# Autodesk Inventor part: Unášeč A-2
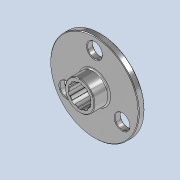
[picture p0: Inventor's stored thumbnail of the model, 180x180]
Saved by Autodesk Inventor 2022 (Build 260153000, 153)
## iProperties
Created: 2025-05
Part Number: Unášeč A-2
Material: Všeobecné
Document SubType Name: Modeling
Designer: jbart
Density: 1 g/cm^3
Appearance: Broušená
Mass: 1373.6 g
Surface Area: 1803.2 cm^2
Volume: 1373.6 cm^3
Author: jbart
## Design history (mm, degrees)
sketch "Náčrt1"
  geometry: L1 (0, 108)-(93.531, -54); L2 (93.531, -54)-(-93.531, -54); L3 (-93.531, -54)-(0, 108); L4 (0, 108)-(0, 0); L5 (0, 0)-(93.531, -54); L6 (0, 0)-(-93.531, -54); C1 r 150 at (0, 0); C2 r 25 at (0, 108); C3 r 25 at (-93.531, -54); C4 r 25 at (93.531, -54); 1 further point
  constraints: 12 end point, 5 coincident, 4 centre point, 1 vertical, 7 other
  dimensions: "d0" = 108 distance of L4.end L1.end; "d1" = 300 diameter of C1; "d2" = 50 diameter of C2; "d3" = 50 diameter of C3; "d4" = 50 diameter of C4
extrude "Vysunutí1" new body sketch "Náčrt1" distance "d5" = 20; taper "d6" = 0 deg
sketch "Náčrt2"
  geometry: C1 r 50 at (0, 0); 1 further point
  constraints: 1 centre point, 1 coincident
  dimensions: "d7" = 100 diameter of C1
extrude "Vysunutí2" join sketch "Náčrt2" distance "d8" = 50; taper "d9" = 0 deg
sketch "Náčrt3"
  geometry: C1 r 36 at (0, 0); 1 further point
  constraints: 1 centre point, 1 coincident
  dimensions: "d10" = 72 diameter of C1
extrude "Vysunutí3" cut sketch "Náčrt3" extent not by distance; stored distance "d11" = 0; taper "d12" = 0 deg
sketch "Náčrt4"
  geometry: L1 (-6, 38.536)-(-6, 35.496); L2 (6, 38.536)-(6, 35.496); L3 (0, 0)-(0, 5); A1 r 36 centre (0, 0) between (-6, 35.496) and (6, 35.496) reference; A2 r 39 centre (0, 0) between (6, 38.536) and (-6, 38.536); 1 further point
  constraints: 6 end point, 4 point on circle, 3 vertical, 1 centre point, 1 coincident, 1 other
  dimensions: "d13" = 78 diameter of A2; "d14" = 12 distance between parallel lines of L2 L1; "d15" = 5 distance of L3.start L3.end
extrude "Vysunutí4" cut sketch "Náčrt4" extent not by distance; stored distance "d16" = 0; taper "d17" = 0 deg
pattern_circular "Kruhové pole1" dims angle "d19" = 360 deg
fillet "Zaoblení1" dims "d21" = 5
chamfer "Zkosení1" distance "d22" = 2; stored, may be unused: second distance "d23" = 2, angle "d24" = 45 deg
chamfer "Zkosení2" distance "d25" = 1; stored, may be unused: second distance "d26" = 2, angle "d27" = 45 deg
node "Těleso1"
